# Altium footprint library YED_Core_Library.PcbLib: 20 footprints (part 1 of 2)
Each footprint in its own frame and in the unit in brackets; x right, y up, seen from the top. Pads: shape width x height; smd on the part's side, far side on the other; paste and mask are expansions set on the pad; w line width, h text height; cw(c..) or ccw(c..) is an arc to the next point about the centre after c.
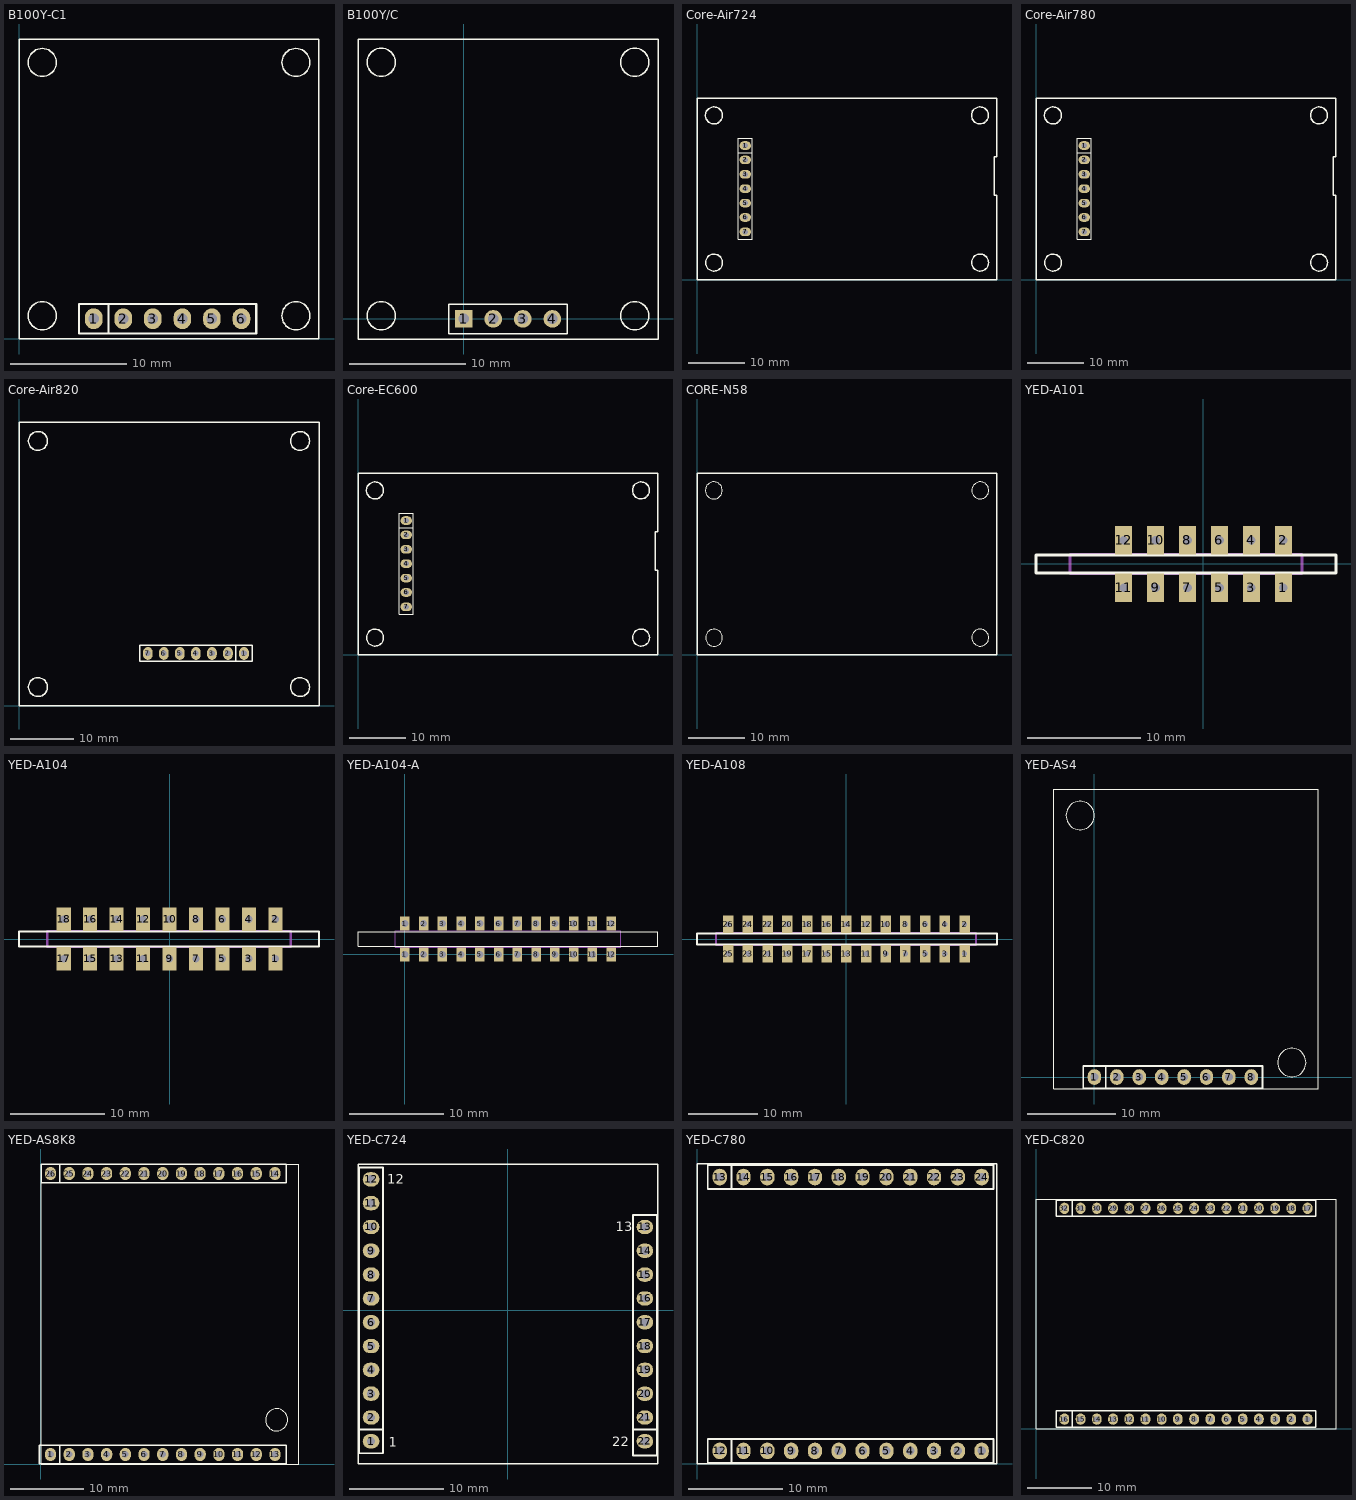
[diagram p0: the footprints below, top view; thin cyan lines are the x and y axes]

## B100Y-C1 [mil]
pads (6):
  oval 60x70 hole 35: 1(253,68.5) 2(353,68.5) 3(453,68.5) 4(553,68.5) 5(653,68.5) 6(753,68.5)
Top Overlay:
  circle w5: c78.74,78.74 r47.24
  circle w5: c937.26,78.74 r47.24
  circle w5: c937.26,936.61 r47.24
  circle w5: c78.74,936.61 r47.24
  lines w5: 0,0 0,1015.75 1015.75,1015.75 1015.75,0 0,0
  lines w7.87: 303,18.5 303,118.5 ; 203,18.5 203,118.5 803,118.5 803,18.5 203,18.5

## B100Y/C [mil]
pads (4):
  rect 60x60 hole 35.43: 1(0,0)
  round 60 hole 35.43: 2(100,0) 3(200,0) 4(300,0)
Top Overlay:
  circle w5: c-279.25,10.63 r47.24
  circle w5: c579.02,10.63 r47.24
  circle w5: c579.02,868.9 r47.24
  circle w5: c-279.25,868.9 r47.24
  lines w5: -357.99,-68.11 657.76,-68.11 657.76,947.64 -357.99,947.64 -357.99,-68.11 ; -50,-50 -50,50 350,50 350,-50 -50,-50

## Core-Air724 [mil]
pads (14):
  oval 70x60 hole 35: 1(335.63,932.09) 2(335.63,832.09) 3(335.63,732.09) 4(335.63,632.09) 5(335.63,532.09) 6(335.63,432.09) 7(335.63,332.09)
  oval 80x60 hole 35: 1(335.63,932.09) 2(335.63,832.09) 3(335.63,732.09) 4(335.63,632.09) 5(335.63,532.09) 6(335.63,432.09) 7(335.63,332.09)
Top Overlay:
  circle w10: c1968.31,1141.89 r59.06
  circle w10: c1968.66,118.31 r59.06
  circle w10: c117.95,1141.54 r59.06
  circle w10: c118.31,117.95 r59.06
  lines w7.87: 285.63,882.09 385.63,882.09 ; 285.63,282.09 385.63,282.09 385.63,982.09 285.63,982.09 285.63,282.09
  lines w10: 0,0 2086.61,0 2086.61,585.63 2066.93,585.63 2066.93,853.35 2086.61,853.35 2086.61,1259.84 0,1259.84 0,0
3D body: height 137.8, standoff -78.74, extent 325.7,820.32 345.34,839.93
3D body: height 147.64, standoff 127.95, extent 325.63,820.39 345.31,839.78
3D body: height 147.64, standoff 127.95, extent 323.63,722.39 343.31,741.78
3D body: height 137.8, standoff -78.74, extent 323.7,722.32 343.34,741.93
3D body: height 137.8, standoff -78.74, extent 323.7,622.32 343.34,641.93
3D body: height 147.64, standoff 127.95, extent 323.63,622.39 343.31,641.78
3D body: height 137.8, standoff -78.74, extent 323.7,425.32 343.35,444.93
3D body: height 147.64, standoff 127.95, extent 323.63,425.39 343.31,444.78
3D body: height 137.8, standoff -78.74, extent 321.7,324.32 341.34,343.93
3D body: height 147.64, standoff 127.95, extent 321.63,324.39 341.31,343.78
3D body: height 137.8, standoff -78.74, extent 326.7,919.33 346.35,938.93
3D body: height 147.64, standoff 127.95, extent 326.62,919.39 346.31,938.77
3D body: height 147.64, standoff 127.95, extent 323.63,525.39 343.31,544.78
3D body: height 137.8, standoff -78.74, extent 323.7,525.32 343.35,544.93
3D body: height 157.48, standoff -78.74, extent 2053.44,601.05 2447.14,837.26
3D body: height 157.48, standoff -78.74, extent 2051.44,604.34 2079.44,834.34
3D body: height -39.37, standoff -78.74, extent 1857.44,701.34 2054.44,738.34
3D body: height -39.37, standoff -78.74, extent 1857.44,604.34 2054.44,641.34
3D body: height 39.37, standoff 0, extent 1857.44,701.34 2054.44,738.34
3D body: height -39.37, standoff -78.74, extent 1857.44,797.34 2054.44,834.34
3D body: height 39.37, standoff 0, extent 1857.44,797.34 2054.44,834.34
3D body: height 39.37, standoff 0, extent 1857.44,604.34 2054.44,641.34

## Core-Air780 [mil]
pads (14):
  oval 70x60 hole 35: 1(335.63,932.09) 2(335.63,832.09) 3(335.63,732.09) 4(335.63,632.09) 5(335.63,532.09) 6(335.63,432.09) 7(335.63,332.09)
  oval 80x60 hole 35: 1(335.63,932.09) 2(335.63,832.09) 3(335.63,732.09) 4(335.63,632.09) 5(335.63,532.09) 6(335.63,432.09) 7(335.63,332.09)
Top Overlay:
  circle w10: c1968.31,1141.89 r59.06
  circle w10: c1968.66,118.31 r59.06
  circle w10: c117.95,1141.54 r59.06
  circle w10: c118.31,117.95 r59.06
  lines w7.87: 285.63,882.09 385.63,882.09 ; 285.63,282.09 385.63,282.09 385.63,982.09 285.63,982.09 285.63,282.09
  lines w10: 0,0 2086.61,0 2086.61,585.63 2066.93,585.63 2066.93,853.35 2086.61,853.35 2086.61,1259.84 0,1259.84 0,0
3D body: height 39.37, standoff 0, extent 1857.44,604.34 2054.44,641.34
3D body: height 39.37, standoff 0, extent 1857.44,797.34 2054.44,834.34
3D body: height -39.37, standoff -78.74, extent 1857.44,797.34 2054.44,834.34
3D body: height 39.37, standoff 0, extent 1857.44,701.34 2054.44,738.34
3D body: height -39.37, standoff -78.74, extent 1857.44,604.34 2054.44,641.34
3D body: height -39.37, standoff -78.74, extent 1857.44,701.34 2054.44,738.34
3D body: height 157.48, standoff -78.74, extent 2051.44,604.34 2079.44,834.34
3D body: height 157.48, standoff -78.74, extent 2053.44,601.05 2447.14,837.26
3D body: height 137.8, standoff -78.74, extent 325.7,820.32 345.34,839.93
3D body: height 147.64, standoff 127.95, extent 325.63,820.39 345.31,839.78
3D body: height 147.64, standoff 127.95, extent 323.63,722.39 343.31,741.78
3D body: height 137.8, standoff -78.74, extent 323.7,722.32 343.34,741.93
3D body: height 137.8, standoff -78.74, extent 323.7,622.32 343.34,641.93
3D body: height 147.64, standoff 127.95, extent 323.63,622.39 343.31,641.78
3D body: height 137.8, standoff -78.74, extent 323.7,425.32 343.35,444.93
3D body: height 147.64, standoff 127.95, extent 323.63,425.39 343.31,444.78
3D body: height 137.8, standoff -78.74, extent 321.7,324.32 341.34,343.93
3D body: height 147.64, standoff 127.95, extent 321.63,324.39 341.31,343.78
3D body: height 137.8, standoff -78.74, extent 326.7,919.33 346.35,938.93
3D body: height 147.64, standoff 127.95, extent 326.62,919.39 346.31,938.77
3D body: height 147.64, standoff 127.95, extent 323.63,525.39 343.31,544.78
3D body: height 137.8, standoff -78.74, extent 323.7,525.32 343.35,544.93

## Core-Air820 [mil]
pads (7):
  oval 60x80 hole 35: 1(1404,328) 2(1304,328) 3(1204,328) 4(1104,328) 5(1004,328) 6(904,328) 7(804,328)
Top Overlay:
  circle w7.87: c118.11,118.11 r59.06
  circle w7.87: c118.11,1653.54 r59.06
  circle w7.87: c1753.89,1653.54 r59.06
  circle w7.87: c1753.89,118.11 r59.06
  lines w7.87: 1354,278 1354,378 ; 0,0 0,1771.65 1872,1771.65 1872,0 0,0 ; 754,278 754,378 1454,378 1454,278 754,278
Bottom Overlay:
  lines w10: 704,1.23 1499.28,1.23
3D body: height 137.8, standoff -78.74, extent 796.24,314.07 815.84,333.72
3D body: height 147.64, standoff 127.95, extent 796.2,314 815.8,333.58
3D body: height 137.8, standoff -78.74, extent 897.24,316.07 916.84,335.72
3D body: height 147.64, standoff 127.95, extent 897.2,316 916.8,335.58
3D body: height 137.8, standoff -78.74, extent 1094.24,316.07 1113.84,335.72
3D body: height 147.64, standoff 127.95, extent 1094.2,316 1113.8,335.58
3D body: height 137.8, standoff -78.74, extent 1391.24,319.07 1410.84,338.72
3D body: height 147.64, standoff 127.95, extent 1391.2,319 1410.8,338.58
3D body: height 137.8, standoff -78.74, extent 1292.24,318.07 1311.84,337.72
3D body: height 147.64, standoff 127.95, extent 1292.2,318 1311.8,337.58
3D body: height 147.64, standoff 127.95, extent 1194.2,316 1213.8,335.58
3D body: height 137.8, standoff -78.74, extent 1194.24,316.07 1213.84,335.72
3D body: height 147.64, standoff 127.95, extent 997.2,316 1016.8,335.58
3D body: height 137.8, standoff -78.74, extent 997.24,316.07 1016.84,335.72

## Core-EC600 [mil]
pads (14):
  oval 80x60 hole 35: 1(335.63,932.09) 2(335.63,832.09) 3(335.63,732.09) 4(335.63,632.09) 5(335.63,532.09) 6(335.63,432.09) 7(335.63,332.09)
  oval 70x60 hole 35: 1(335.63,932.09) 2(335.63,832.09) 3(335.63,732.09) 4(335.63,632.09) 5(335.63,532.09) 6(335.63,432.09) 7(335.63,332.09)
Top Overlay:
  circle w10: c118.31,117.95 r59.06
  circle w10: c117.95,1141.54 r59.06
  circle w10: c1968.66,118.31 r59.06
  circle w10: c1968.31,1141.89 r59.06
  lines w7.87: 285.63,882.09 385.63,882.09 ; 285.63,282.09 285.63,982.09 385.63,982.09 385.63,282.09 285.63,282.09
  lines w10: 0,0 0,1259.84 2086.61,1259.84 2086.61,853.35 2066.93,853.35 2066.93,585.63 2086.61,585.63 2086.61,0 0,0
3D body: height 39.37, standoff 0, extent 1857.44,604.34 2054.44,641.34
3D body: height 39.37, standoff 0, extent 1857.44,797.34 2054.44,834.34
3D body: height -39.37, standoff -78.74, extent 1857.44,797.34 2054.44,834.34
3D body: height 39.37, standoff 0, extent 1857.44,701.34 2054.44,738.34
3D body: height -39.37, standoff -78.74, extent 1857.44,604.34 2054.44,641.34
3D body: height -39.37, standoff -78.74, extent 1857.44,701.34 2054.44,738.34
3D body: height 157.48, standoff -78.74, extent 2051.44,604.34 2079.44,834.34
3D body: height 157.48, standoff -78.74, extent 2053.44,601.05 2447.14,837.26
3D body: height 137.8, standoff -78.74, extent 323.7,525.32 343.35,544.93
3D body: height 147.64, standoff 127.95, extent 323.63,525.39 343.31,544.78
3D body: height 147.64, standoff 127.95, extent 326.62,919.39 346.31,938.77
3D body: height 137.8, standoff -78.74, extent 326.7,919.33 346.35,938.93
3D body: height 147.64, standoff 127.95, extent 321.63,324.39 341.31,343.78
3D body: height 137.8, standoff -78.74, extent 321.7,324.32 341.34,343.93
3D body: height 147.64, standoff 127.95, extent 323.63,425.39 343.31,444.78
3D body: height 137.8, standoff -78.74, extent 323.7,425.32 343.35,444.93
3D body: height 147.64, standoff 127.95, extent 323.63,622.39 343.31,641.78
3D body: height 137.8, standoff -78.74, extent 323.7,622.32 343.34,641.93
3D body: height 137.8, standoff -78.74, extent 323.7,722.32 343.34,741.93
3D body: height 147.64, standoff 127.95, extent 323.63,722.39 343.31,741.78
3D body: height 147.64, standoff 127.95, extent 325.63,820.39 345.31,839.78
3D body: height 137.8, standoff -78.74, extent 325.7,820.32 345.34,839.93

## CORE-N58 [mil]
Top Overlay:
  circle w7.87: c118.31,116.97 r59.06
  circle w7.87: c116.97,1141.54 r59.06
  circle w7.87: c1970.28,1141.73 r59.06
  circle w7.87: c1970.08,118.11 r59.06
  lines w10: 0,0 0,1259.84 2086.61,1259.84 2086.61,0 0,0
3D body: height -39.37, standoff -78.74, extent 1867,431 2064,468
3D body: height -39.37, standoff -78.74, extent 1867,335 2064,372
3D body: height -39.37, standoff -78.74, extent 1867,238 2064,275
3D body: height 157.48, standoff -78.74, extent 2061,238 2089,468
3D body: height 39.37, standoff 0, extent 1867,238 2064,275
3D body: height 39.37, standoff 0, extent 1867,335 2064,372
3D body: height 39.37, standoff 0, extent 1867,431 2064,468
3D body: height 157.25, standoff -78.51, extent 2063,234.71 2456.7,470
3D body: height -39.37, standoff -78.74, extent 1865,971 2062,1008
3D body: height -39.37, standoff -78.74, extent 1865,875 2062,912
3D body: height -39.37, standoff -78.74, extent 1865,778 2062,815
3D body: height 157.48, standoff -78.74, extent 2059,778 2087,1008
3D body: height 39.37, standoff 0, extent 1865,778 2062,815
3D body: height 39.37, standoff 0, extent 1865,875 2062,912
3D body: height 39.37, standoff 0, extent 1865,971 2062,1008
3D body: height 157.25, standoff -78.51, extent 2061,774.71 2454.7,1010

## YED-A101 [mm]
pads (12):
  rect 1.5x2.5 hole 0.762: 1(7.055,-2.1) 2(7.055,2.1) 3(4.233,-2.1) 4(4.233,2.1) 5(1.411,-2.1) 6(1.411,2.1) 7(-1.411,-2.1) 8(-1.411,2.1) 9(-4.233,-2.1) 10(-4.233,2.1) 11(-7.055,-2.1) 12(-7.055,2.1)
Top Overlay:
  lines w0.254: -14.793,-0.8 -14.793,0.8 11.707,0.8 11.707,-0.8 -14.793,-0.8
Mechanical 1:
  lines w0.254: -11.793,-0.85 -11.793,0.85 8.707,0.85 8.707,-0.85 -11.793,-0.85

## YED-A104 [mm]
pads (18):
  rect 1.5x2.5 hole 0.762: 1(11.288,-2.1) 2(11.288,2.1) 3(8.466,-2.1) 4(8.466,2.1) 5(5.644,-2.1) 6(5.644,2.1) 7(2.822,-2.1) 8(2.822,2.1) 9(0,-2.1) 10(0,2.1) 11(-2.822,-2.1) 12(-2.822,2.1) 13(-5.644,-2.1) 14(-5.644,2.1) 15(-8.466,-2.1) 16(-8.466,2.1) 17(-11.288,-2.1) 18(-11.288,2.1)
Top Overlay:
  lines w0.254: -16.06,-0.8 15.94,-0.8 15.94,0.8 -16.06,0.8 -16.06,-0.8
Mechanical 1:
  lines w0.254: -13.06,-0.85 12.94,-0.85 12.94,0.85 -13.06,0.85 -13.06,-0.85

## YED-A104-A [mm]
pads (24):
  rect 1x1.5 hole 0.762: 1(0,0) 1(0,3.3) 2(2,0) 2(2,3.3) 3(4,0) 3(4,3.3) 4(6,0) 4(6,3.3) 5(8,0) 5(8,3.3) 6(10,0) 6(10,3.3) 7(12,0) 7(12,3.3) 8(14,0) 8(14,3.3) 9(16,0) 9(16,3.3) 10(18,0) 10(18,3.3) 11(20,0) 11(20,3.3) 12(22,0) 12(22,3.3)
Top Overlay:
  lines w0.127: -5,0.85 -5,2.45 27,2.45 27,0.85 -5,0.85
Mechanical 1:
  lines w0.127: -1,0.75 23,0.75 23,2.55 -1,2.55 -1,0.75

## YED-A108 [mm]
pads (26):
  rect 1.5x2.5 hole 0.762: 1(16.932,-2.1) 2(16.932,2.1) 3(14.11,-2.1) 4(14.11,2.1) 5(11.288,-2.1) 6(11.288,2.1) 7(8.466,-2.1) 8(8.466,2.1) 9(5.644,-2.1) 10(5.644,2.1) 11(2.822,-2.1) 12(2.822,2.1) 13(0,-2.1) 14(0,2.1) 15(-2.822,-2.1) 16(-2.822,2.1) 17(-5.644,-2.1) 18(-5.644,2.1) 19(-8.466,-2.1) 20(-8.466,2.1) 21(-11.288,-2.1) 22(-11.288,2.1) 23(-14.11,-2.1) 24(-14.11,2.1) 25(-16.932,-2.1) 26(-16.932,2.1)
Top Overlay:
  lines w0.254: -21.416,-0.8 21.584,-0.8 21.584,0.8 -21.416,0.8 -21.416,-0.8
Mechanical 1:
  lines w0.254: -18.704,-0.85 -18.704,0.85 18.584,0.85 18.584,-0.85 -18.704,-0.85

## YED-AS4 [mil]
pads (8):
  oval 60x70 hole 35: 1(0,0) 2(100,0) 3(200,0) 4(300,0) 5(400,0) 6(500,0) 7(600,0) 8(700,0)
Top Overlay:
  circle w5: c880.99,64.96 r62.99
  circle w5: c-63.89,1167.32 r62.99
  lines w5: -182,-53.15 999.1,-53.15 999.1,1285.43 -182,1285.43 -182,-53.15
  lines w7.87: 50,-50 50,50 ; 354.33,-50 -50,-50 ; -50,-50 750,-50 750,50 -50,50 -50,-50
3D body: height 43.31, standoff 0, extent -46.83,-45.99 144.6,45.63
3D body: height 354.33, standoff -86.61, extent -22.36,-21.61 21.16,22
3D body: height 354.33, standoff -86.61, extent 77.64,-21.61 121.16,22
3D body: height 43.31, standoff 0, extent 153.17,-45.99 344.6,45.63
3D body: height 354.33, standoff -86.61, extent 177.64,-21.61 221.16,22
3D body: height 354.33, standoff -86.61, extent 277.64,-21.61 321.16,22
3D body: height 43.31, standoff 0, extent 353.17,-45.99 544.6,45.63
3D body: height 354.33, standoff -86.61, extent 377.64,-21.61 421.16,22
3D body: height 354.33, standoff -86.61, extent 477.64,-21.61 521.16,22
3D body: height 43.31, standoff 0, extent 553.17,-45.99 744.6,45.63
3D body: height 354.33, standoff -86.61, extent 577.64,-21.61 621.16,22
3D body: height 354.33, standoff -86.61, extent 677.64,-21.61 721.16,22
3D body "YED-AS4.step": height 157.48, standoff -370.53, extent -182,-53.15 999.1,1285.43

## YED-AS8K8 [mil]
pads (26):
  oval 60x70 hole 35: 1(51.18,51.18) 2(151.18,51.18) 3(251.18,51.18) 4(351.18,51.18) 5(451.18,51.18) 6(551.18,51.18) 7(651.18,51.18) 8(751.18,51.18) 9(851.18,51.18) 10(951.18,51.18) 11(1051.18,51.18) 12(1151.18,51.18) 13(1251.18,51.18) 14(1251,1553) 15(1151,1553) 16(1051,1553) 17(951,1553) 18(851,1553) 19(751,1553) 20(651,1553) 21(551,1553) 22(451,1553) 23(351,1553) 24(251,1553) 25(151,1553) 26(51,1553)
Top Overlay:
  circle w5: c1259.84,236.22 r59.06
  lines w5: 0,1.18 0.39,1.57 0.39,1603 1.39,1604 1377.95,1604 1377.95,0 1.18,0
  lines w7.87: 101,1503 101,1603 ; 101.18,1.18 101.18,101.18 ; -8.82,1.18 -8.82,101.18 1311.18,101.18 1311.18,1.18 -8.82,1.18 ; 0.39,1503 0.39,1603 1311,1603 1311,1503 0.39,1503

## YED-C724 [mil]
pads (22):
  oval 70x60 hole 35: 1(-575.01,-549.97) 2(-575.01,-449.97) 3(-575.01,-349.97) 4(-575.01,-249.97) 5(-575.01,-149.97) 6(-575.01,-49.97) 7(-575.01,50.03) 8(-575.01,150.03) 9(-575.01,250.03) 10(-575.01,350.03) 11(-575.01,450.03) 12(-575.01,550.03) 13(575.01,349.97) 14(575.01,249.97) 15(575.01,149.97) 16(575.01,49.97) 17(575.01,-50.03) 18(575.01,-150.03) 19(575.01,-250.03) 20(575.01,-350.03) 21(575.01,-450.03) 22(575.01,-550.03)
Top Overlay:
  lines w6: -629.86,-645.37 -629.86,614.47 629.98,614.47 629.98,-645.37 -629.86,-645.37
  lines w7.87: -625.01,-499.97 -525.01,-499.97 ; 525.01,-500.03 625.01,-500.03 ; -625.01,-599.97 -525.01,-599.97 -525.01,600.03 -625.01,600.03 -625.01,-599.97 ; 525.01,-610.03 625.01,-610.03 625.01,399.83 525.01,399.83 525.01,-610.03
  text "1" at -501,-573 h40
  text "12" at -507,532 h40
  text "13" at 452,332 h40
  text "22" at 437,-571 h40

## YED-C780 [mil]
pads (24):
  oval 60x70 hole 35: 1(1195.4,54.96) 2(1095.4,54.96) 3(995.4,54.96) 4(895.4,54.96) 5(795.4,54.96) 6(695.4,54.96) 7(595.4,54.96) 8(495.4,54.96) 9(395.4,54.96) 10(295.4,54.96) 11(195.4,54.96) 12(95.4,54.96) 13(95.4,1204.99) 14(195.4,1204.99) 15(295.4,1204.99) 16(395.4,1204.99) 17(495.4,1204.99) 18(595.4,1204.99) 19(695.4,1204.99) 20(795.4,1204.99) 21(895.4,1204.99) 22(995.4,1204.99) 23(1095.4,1204.99) 24(1195.4,1204.99)
Top Overlay:
  lines w5.98: 0,0 1259.84,0 1259.84,1259.84 0,1259.84 0,0
  lines w7.87: 145.4,4.96 145.4,104.96 ; 145.4,1154.99 145.4,1254.99 ; 45.4,4.96 1245.4,4.96 1245.4,104.96 45.4,104.96 45.4,4.96 ; 45.4,1154.99 1245.4,1154.99 1245.4,1254.99 45.4,1254.99 45.4,1154.99

## YED-C820 [mil]
pads (32):
  oval 60x70 hole 35: 1(1675,60.48) 2(1575,60.48) 3(1475,60.48) 4(1375,60.48) 5(1275,60.48) 6(1175,60.48) 7(1075,60.48) 8(975,60.48) 9(875,60.48) 10(775,60.48) 11(675,60.48) 12(575,60.48) 13(475,60.48) 14(375,60.48) 15(275,60.48) 16(175,60.48) 17(1675,1360.48) 18(1575,1360.48) 19(1475,1360.48) 20(1375,1360.48) 21(1275,1360.48) 22(1175,1360.48) 23(1075,1360.48) 24(975,1360.48) 25(875,1360.48) 26(775,1360.48) 27(675,1360.48) 28(575,1360.48) 29(475,1360.48) 30(375,1360.48) 31(275,1360.48) 32(175,1360.48)
Top Overlay:
  lines w6: 0,0 0,1417.32 1850.39,1417.32 1850.39,0 0,0
  lines w7.87: 225,10.48 225,110.48 ; 225,1310.48 225,1410.48 ; 125,10.48 1725,10.48 1725,110.48 125,110.48 125,10.48 ; 125,1310.48 1725,1310.48 1725,1410.48 125,1410.48 125,1310.48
